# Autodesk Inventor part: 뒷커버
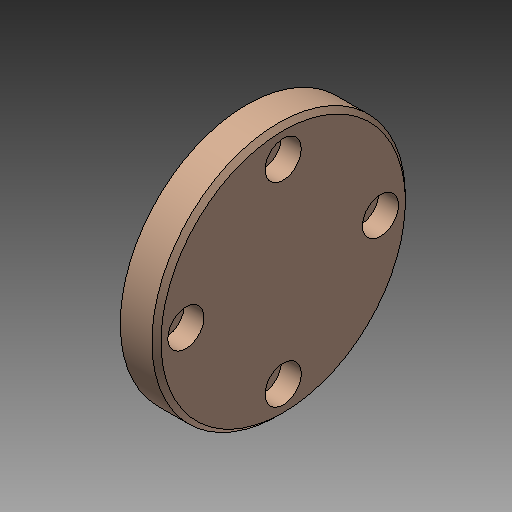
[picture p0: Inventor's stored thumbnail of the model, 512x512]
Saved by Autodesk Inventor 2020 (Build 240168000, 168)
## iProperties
Created: 2024-01
Part Number: 뒷커버
Material: 알루미늄 6061
Document SubType Name: Modeling
Designer: mdu-01
Density: 1 g/cm^3
Appearance: 기본값(1)
Author: mdu-01
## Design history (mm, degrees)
sketch "스케치1"
  geometry: L1 (0, 0)-(-9, 0); L2 (-9, 0)-(-9, 14.5); L3 (-9, 14.5)-(-12, 14.5); L4 (-12, 14.5)-(-12, 16.5); L5 (-11, 17.5)-(-8, 17.5); L6 (-8, 17.5)-(-8, 28); L7 (-8, 28)-(-1, 28); L8 (0, 27)-(0, 0); L9 (-12, 16.5)-(-11, 17.5); L10 (-1, 28)-(0, 27); 2 further points
  constraints: 20 end point, 6 parallel, 4 point on line, 1 horizontal, 1 perpendicular
  dimensions: "d0" = 56 diameter of L7 L1; "d2" = 8 distance between parallel lines of L8 L6; "d3" = 3 distance between parallel lines of L2 L4; "d4" = 4 distance between parallel lines of L6 L4; "d5" = 29 diameter of L3 L1; "d6" = 35 diameter of L5 L1; "d7" = 1 distance of L4.end point (-12, 17.5); "d8" = 1 distance of L5.start point (-12, 17.5) (= d7); "d9" = 1 distance of L7.end point (0, 28) (= d7); "d10" = 1 distance of L8.start point (0, 28) (= d9)
revolve "회전1" sketch "스케치1" stored, may be unused: angle "d11" = 90 deg
sketch "스케치2" dims "d12" = 43
  geometry: 3 further points
  constraints: 2 vertical alignment, 1 coincident, 2 other
hole "구멍1" sketch "스케치2" at (0, 21.5) diameter "d13" = 4.5; stored, may be unused: countersink angle "d17" = 90 deg, drill point angle "d19" = 118 deg; dims "d14" = 6, "d15" = 8, "d16" = 4.4, "d18" = 8
node "솔리드1"
pattern_circular "원형 패턴1" dims angle "d21" = 360 deg
